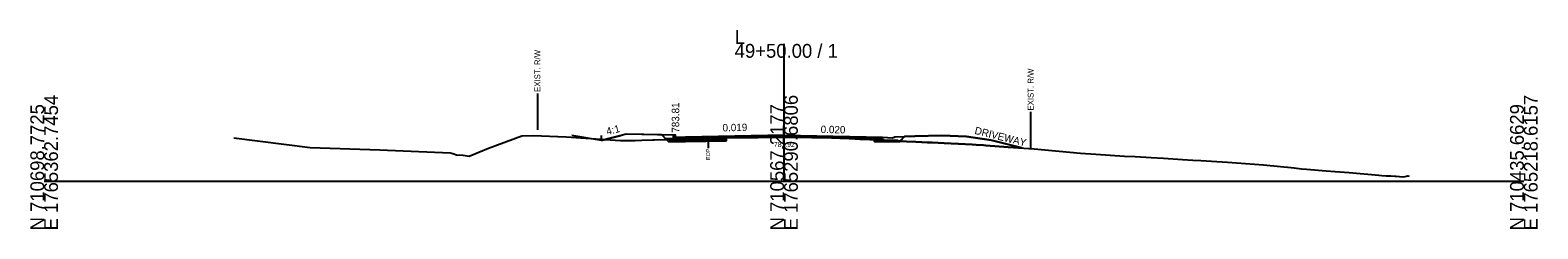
# Model space of a CAD drawing. Extents: x -26 to 5303, y -10 to 9578.
# Drawn here: x 2997.2 to 3302.8, y 9490.3 to 9530.6 of the extents above; entities that cross this region are included whole.
import ezdxf

# ---------------------------------------------------------------- set-up
doc = ezdxf.new("R2010")
doc.units = 0
for name, color, linetype in [('Default', 7, 'Continuous'), ('Exist CMT Pavement', 7, 'Continuous'), ('Exist Cross Section Cell', 7, 'Continuous'), ('Exist XS Ground Line', 7, 'Continuous'), ('Old_Level_10', 7, 'Continuous'), ('Old_Level_3', 7, 'Continuous'), ('Prop CMT Conc Surface', 7, 'Continuous'), ('Prop CMT Concrete Structures', 7, 'Continuous'), ('Prop CMT Pvmt Course 1', 7, 'Continuous'), ('Prop CMT Pvmt Course 1 CG', 7, 'Continuous'), ('Prop CMT Pvmt Course 2', 7, 'Continuous'), ('Prop CMT Pvmt Course 3', 7, 'Continuous'), ('Prop CMT Pvmt Surface', 7, 'Continuous'), ('Prop CMT Slope Grass', 7, 'Continuous'), ('Prop CMT Subgrade Earthwork', 7, 'Continuous'), ('Prop XS Earthwork Shape', 7, 'Continuous'), ('Prop XS Hydro Elevations', 7, 'Continuous'), ('Prop XS SE Text', 7, 'Continuous'), ('Prop XS Side Slope Text', 7, 'Continuous'), ('Prop XS Wedging', 7, 'Continuous'), ('Scratch_Level_2', 7, 'Continuous')]:
    doc.layers.add(name, color=color, linetype=linetype)

msp = doc.modelspace()

# ---------------------------------------------------------------- linework, layer by layer
at = {"layer": 'Exist CMT Pavement'}
msp.add_lwpolyline([(3138.25, 9508.81), (3138.25, 9508.81), (3139.05, 9508.82), (3139.7, 9508.83), (3141.27, 9508.85), (3142.55, 9508.86), (3143.61, 9508.86), (3144.77, 9508.87), (3145.4, 9508.88), (3147.57, 9508.91), (3148.45, 9508.92), (3150.3, 9508.92), (3151.73, 9508.92), (3152.14, 9508.92), (3153.98, 9508.89), (3155.13, 9508.88), (3155.65, 9508.86), (3156.21, 9508.86), (3156.8, 9508.85), (3159.65, 9508.79), (3161.34, 9508.73), (3162.51, 9508.67), (3163.19, 9508.63), (3164.43, 9508.57), (3165.03, 9508.54), (3165.36, 9508.53), (3166.48, 9508.47), (3168.32, 9508.39)], dxfattribs=at)
at = {"layer": 'Exist Cross Section Cell'}
for p, q in [((3150, 9500), (3150, 9527.81)), ((3000, 9500), (3150, 9500)), ((3150, 9500), (3300, 9500))]:
    msp.add_line(p, q, dxfattribs=at)
at = {"layer": 'Exist XS Ground Line'}
msp.add_lwpolyline([(3038.44, 9508.75), (3053.9, 9506.84), (3068.07, 9506.35), (3082.3, 9505.7), (3082.84, 9505.59), (3083.62, 9505.3), (3084.95, 9505.23), (3086.17, 9505.04), (3090.06, 9506.67), (3096.86, 9509.16), (3099.11, 9509.27), (3105.83, 9508.94), (3116.82, 9508.2), (3117.83, 9508.21), (3118.96, 9508.22), (3119.8, 9508.24), (3121.2, 9508.27), (3134.6, 9508.73), (3135.72, 9508.76), (3136.07, 9508.77), (3136.85, 9508.79), (3137.27, 9508.8), (3137.68, 9508.8), (3138.25, 9508.81), (3139.05, 9508.82), (3139.7, 9508.83), (3141.27, 9508.85), (3142.55, 9508.86), (3143.61, 9508.86), (3145.4, 9508.88), (3147.57, 9508.91), (3148.45, 9508.92), (3150.3, 9508.92), (3151.73, 9508.92), (3152.14, 9508.92), (3153.98, 9508.89), (3155.13, 9508.88), (3155.65, 9508.86), (3156.21, 9508.86), (3156.8, 9508.85), (3159.65, 9508.79), (3160.18, 9508.77), (3162.51, 9508.67), (3164.43, 9508.57), (3165.36, 9508.53), (3166.48, 9508.47), (3168.21, 9508.4), (3169.63, 9508.33), (3170.55, 9508.28), (3171.06, 9508.25), (3172.39, 9508.19), (3173.91, 9508.08), (3174.24, 9508.06), (3174.83, 9508.04), (3176.76, 9507.95), (3179.09, 9507.84), (3179.61, 9507.81), (3180.04, 9507.8), (3182.46, 9507.69), (3185.31, 9507.57), (3187.13, 9507.48), (3188.16, 9507.42), (3188.97, 9507.36), (3190.44, 9507.27), (3190.89, 9507.24), (3195.46, 9506.89), (3200.74, 9506.56), (3210.11, 9505.69), (3213.21, 9505.45), (3219.02, 9505.08), (3221.17, 9504.97), (3224.46, 9504.81), (3226.97, 9504.66), (3230.8, 9504.38), (3232.88, 9504.24), (3234.53, 9504.17), (3239.9, 9503.83), (3247.2, 9503.27), (3253.41, 9502.7), (3254.95, 9502.49), (3255.93, 9502.42), (3259.91, 9502.07), (3261.72, 9501.96), (3264.61, 9501.77), (3270.58, 9501.17), (3271.19, 9501.15), (3272.08, 9501.06), (3273.06, 9501.06), (3273.82, 9501.02), (3274.14, 9501.02), (3275.45, 9500.84), (3275.93, 9500.9), (3276.48, 9501.04), (3276.72, 9501.01)], dxfattribs=at)
at = {"layer": 'Old_Level_10'}
for p, q in [((3100, 9517.79), (3100, 9510.39)), ((3200, 9514.01), (3200, 9506.61)), ((3134.6, 9508.73), (3134.6, 9506.68))]:
    msp.add_line(p, q, dxfattribs=at)
at = {"layer": 'Prop CMT Conc Surface'}
for points in [[(3128, 9508.81), (3128, 9509.31), (3127.5, 9509.31)], [(3130, 9508.93), (3128, 9508.81)]]:
    msp.add_lwpolyline(points, dxfattribs=at)
at = {"layer": 'Prop CMT Concrete Structures'}
for points in [[(3130, 9508.93), (3128, 9508.81), (3128, 9509.31), (3127.5, 9509.31)], [(3127.5, 9509.31), (3127.5, 9508.3), (3130, 9508.35)], [(3130, 9508.35), (3130, 9508.93)]]:
    msp.add_lwpolyline(points, dxfattribs=at)
at = {"layer": 'Prop CMT Pvmt Course 1'}
for points in [[(3150, 9509.31), (3130, 9508.93)], [(3130, 9508.93), (3130, 9508.68)], [(3130, 9508.68), (3138.25, 9508.84)], [(3138.25, 9508.84), (3150, 9509.06)], [(3138.25, 9508.84), (3138.25, 9508.84)], [(3150, 9509.06), (3150, 9509.31)], [(3150, 9509.31), (3170, 9508.91)], [(3150, 9509.06), (3150, 9509.06), (3150, 9509.06)], [(3168.32, 9508.7), (3150, 9509.06)], [(3168.32, 9508.7), (3168.32, 9508.7)], [(3170, 9508.66), (3168.32, 9508.7)], [(3170, 9508.91), (3170, 9508.66)], [(3170, 9508.66), (3170, 9508.66)]]:
    msp.add_lwpolyline(points, dxfattribs=at)
at = {"layer": 'Prop CMT Pvmt Course 1 CG'}
for points in [[(3130, 9508.35), (3127, 9508.29), (3126.66, 9507.95)], [(3126.66, 9507.95), (3130, 9508.01)], [(3130, 9508.01), (3130, 9508.35)], [(3170, 9508.33), (3173, 9508.27), (3173.34, 9507.93)], [(3173.34, 9507.93), (3170, 9508)]]:
    msp.add_lwpolyline(points, dxfattribs=at)
at = {"layer": 'Prop CMT Pvmt Course 2'}
for points in [[(3138.25, 9508.84), (3130, 9508.68)], [(3130, 9508.68), (3130, 9508.35)], [(3130, 9508.35), (3138.25, 9508.5)], [(3138.25, 9508.5), (3138.25, 9508.84)], [(3168.32, 9508.36), (3168.32, 9508.7)], [(3168.32, 9508.7), (3170, 9508.66)], [(3170, 9508.33), (3168.32, 9508.36)], [(3170, 9508.33), (3170, 9508.66)]]:
    msp.add_lwpolyline(points, dxfattribs=at)
at = {"layer": 'Prop CMT Pvmt Course 3'}
for points in [[(3138.25, 9508.5), (3130, 9508.35)], [(3130, 9508.35), (3130, 9508.01)], [(3130, 9508.01), (3138.25, 9508.17)], [(3138.25, 9508.17), (3138.25, 9508.5)], [(3168.32, 9508.03), (3168.32, 9508.36)], [(3168.32, 9508.36), (3170, 9508.33)], [(3170, 9508), (3168.32, 9508.03)], [(3170, 9508), (3170, 9508.33)]]:
    msp.add_lwpolyline(points, dxfattribs=at)
at = {"layer": 'Prop CMT Pvmt Surface'}
for p, q in [((3170, 9508.91), (3172, 9508.79)), ((3172, 9508.79), (3172.5, 9508.96)), ((3172.5, 9508.96), (3176.5, 9509.12)), ((3176.5, 9509.12), (3182, 9509.23)), ((3182, 9509.23), (3187, 9509.03)), ((3187, 9509.03), (3192, 9508.28)), ((3192, 9508.28), (3198.25, 9506.72))]:
    msp.add_line(p, q, dxfattribs=at)
for points in [[(3150, 9509.31), (3130, 9508.93)], [(3150, 9509.31), (3170, 9508.91)]]:
    msp.add_lwpolyline(points, dxfattribs=at)
at = {"layer": 'Prop CMT Slope Grass'}
msp.add_lwpolyline([(3127.5, 9509.31), (3118, 9509.5), (3113.65, 9508.41)], dxfattribs=at)
at = {"layer": 'Prop CMT Subgrade Earthwork'}
for p, q in [((3138.25, 9508.17), (3138.25, 9508.81)), ((3168.32, 9508.03), (3168.32, 9508.39))]:
    msp.add_line(p, q, dxfattribs=at)
for points in [[(3130, 9508.01), (3126.66, 9507.95), (3125.25, 9509.36)], [(3138.25, 9508.17), (3130, 9508.01)], [(3168.32, 9508.03), (3170, 9508)], [(3170, 9508), (3173.34, 9507.93), (3174.45, 9509.04)]]:
    msp.add_lwpolyline(points, dxfattribs=at)
at = {"layer": 'Prop XS Earthwork Shape'}
for p, q in [((3116.99, 9509.25), (3113.65, 9508.41)), ((3113.65, 9508.41), (3116.82, 9508.2)), ((3126, 9508.61), (3125.25, 9509.36)), ((3126.17, 9508.44), (3126, 9508.61))]:
    msp.add_line(p, q, dxfattribs=at)
for points in [[(3116.82, 9508.2), (3117.83, 9508.21), (3118.96, 9508.22), (3119.8, 9508.24), (3121.2, 9508.27), (3126.17, 9508.44)], [(3125.25, 9509.36), (3118, 9509.5), (3116.99, 9509.25)]]:
    msp.add_lwpolyline(points, dxfattribs=at)
for points in [[(3133.41, 9508.73), (3134.6, 9508.73), (3135.72, 9508.76), (3136.07, 9508.77), (3136.85, 9508.79), (3137.27, 9508.8), (3137.68, 9508.8), (3138.25, 9508.81), (3138.25, 9508.17), (3130, 9508.01), (3126.66, 9507.95), (3126, 9508.61), (3126.96, 9508.65)], [(3138.25, 9508.17), (3130, 9508.01), (3126.66, 9507.95), (3126, 9508.61), (3126.96, 9508.65), (3133.41, 9508.73), (3134.6, 9508.73), (3135.72, 9508.76), (3136.07, 9508.77), (3136.85, 9508.79), (3137.27, 9508.8), (3137.68, 9508.8), (3138.25, 9508.81)], [(3168.32, 9508.39), (3169.63, 9508.33), (3171.06, 9508.25), (3172.39, 9508.19), (3173.52, 9508.11), (3173.34, 9507.93), (3170, 9508), (3168.32, 9508.03)], [(3168.32, 9508.03), (3170, 9508), (3173.34, 9507.93), (3173.52, 9508.11), (3172.39, 9508.19), (3171.06, 9508.25), (3169.63, 9508.33), (3168.32, 9508.39)], [(3187, 9509.03), (3192, 9508.28), (3198.25, 9506.72), (3195.46, 9506.89), (3190.89, 9507.24), (3190.44, 9507.27), (3188.97, 9507.36), (3188.16, 9507.42), (3185.39, 9507.56), (3182.46, 9507.69), (3180.04, 9507.8), (3179.61, 9507.81), (3177.92, 9507.89), (3176.76, 9507.95), (3174.83, 9508.04), (3173.91, 9508.08), (3173.52, 9508.11), (3174.45, 9509.04), (3176.5, 9509.12), (3182, 9509.23)], [(3179.61, 9507.81), (3180.04, 9507.8), (3182.46, 9507.69), (3185.39, 9507.56), (3188.16, 9507.42), (3188.97, 9507.36), (3190.44, 9507.27), (3190.89, 9507.24), (3195.46, 9506.89), (3198.25, 9506.72), (3192, 9508.28), (3187, 9509.03), (3182, 9509.23), (3176.5, 9509.12), (3174.45, 9509.04), (3173.52, 9508.11), (3173.91, 9508.08), (3174.83, 9508.04), (3176.76, 9507.95), (3177.92, 9507.89)]]:
    msp.add_lwpolyline(points, close=True, dxfattribs=at)
at = {"layer": 'Prop XS Wedging'}
for points in [[(3138.25, 9508.81), (3138.25, 9508.84), (3139.05, 9508.85), (3139.7, 9508.87), (3141.27, 9508.9), (3142.55, 9508.92), (3143.61, 9508.94), (3144.77, 9508.96), (3145.4, 9508.98), (3147.57, 9509.02), (3148.45, 9509.03), (3150, 9509.06), (3150.3, 9509.06), (3151.73, 9509.03), (3152.14, 9509.02), (3153.98, 9508.98), (3155.13, 9508.96), (3155.65, 9508.95), (3156.2, 9508.94), (3156.8, 9508.93), (3159.65, 9508.87), (3161.34, 9508.84), (3162.51, 9508.81), (3163.18, 9508.8), (3164.43, 9508.78), (3165.03, 9508.76), (3165.36, 9508.76), (3166.48, 9508.73), (3168.21, 9508.7), (3168.21, 9508.4), (3166.48, 9508.48), (3165.36, 9508.53), (3165.03, 9508.54), (3164.43, 9508.57), (3163.18, 9508.63), (3162.51, 9508.67), (3161.34, 9508.73), (3159.65, 9508.79), (3156.8, 9508.85), (3156.2, 9508.86), (3155.65, 9508.86), (3155.13, 9508.88), (3153.98, 9508.89), (3152.14, 9508.92), (3151.73, 9508.92), (3150.3, 9508.92), (3150, 9508.92), (3148.45, 9508.92), (3147.57, 9508.91), (3145.4, 9508.88), (3144.77, 9508.87), (3143.61, 9508.86), (3142.55, 9508.86), (3141.27, 9508.84), (3139.7, 9508.83), (3139.05, 9508.82)], [(3164.32, 9508.57), (3164.52, 9508.77), (3165.03, 9508.76), (3165.36, 9508.76), (3166.48, 9508.73), (3168.21, 9508.7), (3168.21, 9508.4), (3166.48, 9508.48), (3165.36, 9508.53), (3165.03, 9508.54), (3164.43, 9508.57)]]:
    msp.add_lwpolyline(points, close=True, dxfattribs=at)
at = {"layer": 'Scratch_Level_2'}
for q in [(3106.95, 9509.25), (3112.99, 9509.25), (3116.99, 9509.25)]:
    msp.add_line((3112.99, 9508.25), q, dxfattribs=at)

# ---------------------------------------------------------------- texts
at = {"layer": 'Default'}
msp.add_text('-', height=0.0001, dxfattribs=at).set_placement((3000, 9500))
at = {"layer": 'Exist Cross Section Cell'}
for s, p in [('L', (3140, 9527.81)), ('49+50.00 / 1', (3140, 9525.01))]:
    msp.add_text(s, height=2.8, dxfattribs=at).set_placement(p)
for s, p in [('E 1765362.7454', (3002.8, 9490)), ('E 1765290.6806', (3152.8, 9490)), ('E 1765218.6157', (3302.8, 9490)), ('N 710698.7725', (3000, 9490)), ('N 710567.2177', (3150, 9490)), ('N 710435.6629', (3300, 9490))]:
    msp.add_text(s, height=2.8, rotation=90, dxfattribs=at).set_placement(p)
at = {"layer": 'Old_Level_10'}
for s, height, p in [('EXIST. R/W', 1.181, (3100.59, 9518.09)), ('EXIST. R/W', 1.181, (3200.59, 9514.31)), ('EOP', 0.787, (3134.99, 9504.28))]:
    msp.add_text(s, height=height, rotation=90, dxfattribs=at).set_placement(p)
at = {"layer": 'Old_Level_3'}
msp.add_text('783.92', height=1, dxfattribs=at).set_placement((3147.96, 9506.92))
at = {"layer": 'Prop XS Hydro Elevations'}
msp.add_text('783.81', height=1.5, rotation=90, dxfattribs=at).set_placement((3128.75, 9509.81))
at = {"layer": 'Prop XS SE Text'}
for s, rotation, p in [('0.019', 1.1017, (3137.55, 9510.07)), ('0.020', 358.8542, (3157.42, 9509.75))]:
    msp.add_text(s, height=1.5, rotation=rotation, dxfattribs=at).set_placement(p)
at = {"layer": 'Prop XS Side Slope Text'}
for s, rotation, p in [('4:1', 14.0362, (3114.16, 9509.31)), ('DRIVEWAY', 345.9638, (3188.54, 9509.6))]:
    msp.add_text(s, height=1.5, rotation=rotation, dxfattribs=at).set_placement(p)

doc.saveas('drawing.dxf')
